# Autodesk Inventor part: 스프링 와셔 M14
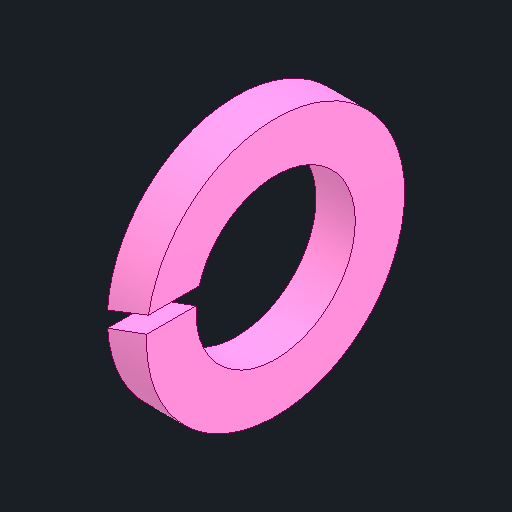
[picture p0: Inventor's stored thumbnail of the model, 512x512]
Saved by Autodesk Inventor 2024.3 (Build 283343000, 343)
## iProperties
Created: 2025-07
Part Number: 스프링 와셔 M14
Material: 강철, 연강
Description: 스프링 잠금 와셔
Document SubType Name: Modeling
Designer: user
Density: 7.85 g/cm^3
Appearance: 기본값
Author: jhkim
Sending System: Autodesk Inventor 2026
Preprocessor: ST-DEVELOPER v20.1
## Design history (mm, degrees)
feature "Solid1"
node "솔리드1"
